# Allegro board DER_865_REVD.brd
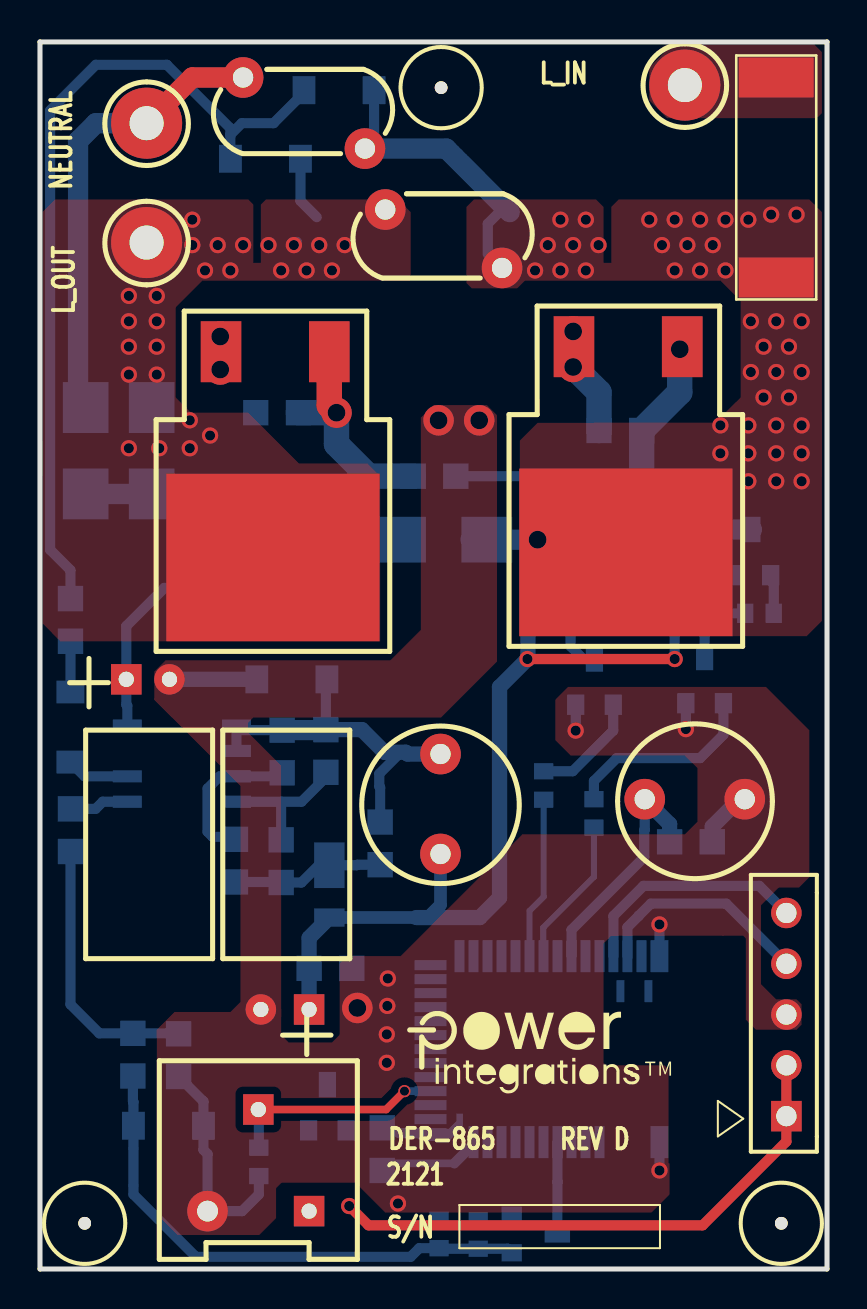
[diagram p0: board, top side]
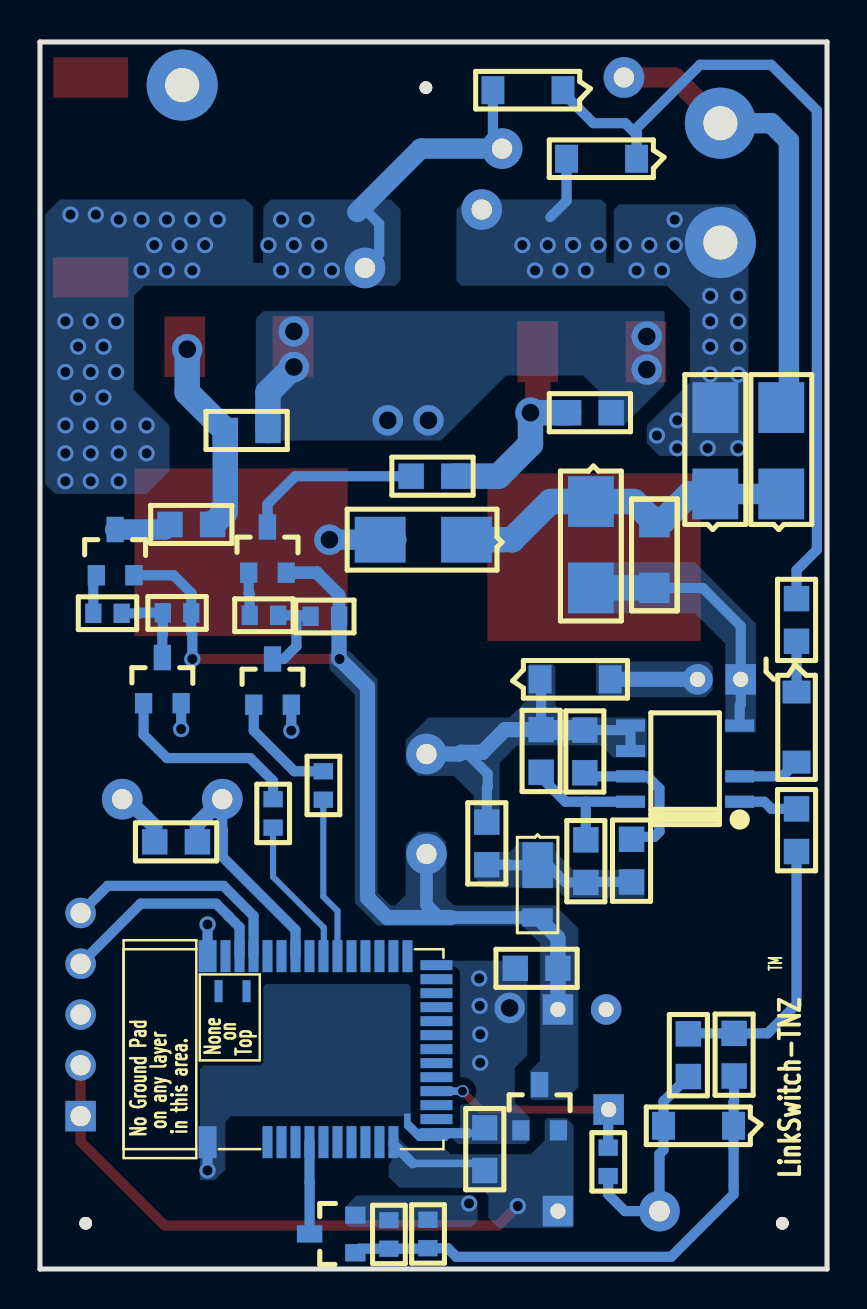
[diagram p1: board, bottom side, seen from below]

Outline 39.37 x 61.37 mm; copper layers: TOP, BOTTOM. Coordinates in mm from the lower left corner of the outline.
Outline path: 0,61.37 0,0 39.37,0 39.37,61.37 0,61.37

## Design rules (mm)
constraint set DEFAULT: min track width 0.508

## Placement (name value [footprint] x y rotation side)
C1  10 uF  [PISMC0805]  17.02 20.22 90 bottom
C2  100 nF  [PISMC0805]  12.12 24.82 90 bottom
C3  2.2 uF  [PIPOLCAPCYLD250LS100030]  6.73 29.49 180 top
C4  100 uF  [PIPOLCAPCYLD250LS100030#2]  11.05 12.98 0 top
C5  1 uF  [PISMC0805]  13.46 15.04 0 bottom
C6  10 uF  [PISMC0805]  17.12 7.06 270 bottom
C7  100 pF  [PISMC0603]  21.92 1.02 90 bottom
C8  100 pf  [PISMC0805]  6.93 11.76 270 bottom
C9  0.1 uF  [PISMC0805]  31.5 21.36 0 bottom
C10  100 nF  [PISMC0603]  10.95 4.65 90 bottom
D1  US2MA  [PISMDO214AC12]  2.29 38.76 90 bottom
D2  US2MA  [PISMDO214AC12]  18.03 36.47 0 bottom
D3  US2MA  [PISMDO214AC12]  5.59 38.76 90 bottom
D4  DFLR1600-7  [PISMDDFLR120012]  14.48 20.22 90 bottom
D5  SM4007PL-TP  [PI_SM_SOD-123_12]  9.53 55.52 0 bottom
D7  UFM15PL-TP  [PI_SM_SOD-123_12]  14.35 29.49 180 bottom
D8  SM4007PL-TP  [PI_SM_SOD-123_12]  13.21 58.95 0 bottom
F1  10 A  [PISMFUSE10P1X3P0]  36.83 59.59 270 top
J1  CON5  [PI_MOLEX_5]  37.34 7.65 90 top
L1  2.2 mH  [PI_CHOKE_2P_LS200D300]  20.04 25.75 270 top
MP1  Post, Round, 5mmL, NYL  [PISRSPACER_D125]  20.07 59.08 0 top
MP2  Post, Round, 5mmL, NYL  [PISRSPACER_D125]  2.24 2.29 0 top
MP3  Post, Round, 5mmL, NYL  [PISRSPACER_D125]  37.08 2.29 0 top
NOREF  -  []  18.39 13.34 0 top
NOREF#2  -  []  0 0 90 top
NOREF#3  -  []  -150.78 54.64 0 top
NOREF#4  -  []  -228.6 -144.37 0 top
NOREF#5  -  []  0 61.37 0 top
ON/OFF  SPST  (NO)  [PI_SWITCH_SPST_RND]  30.25 23.49 270 top
Q1  MMBT4403-7-F  [PISMSOT23123_1]  27.05 34.82 180 bottom
Q2  SIHB065N60E-GE3  [PISMDD2PAK]  14.48 45.87 180 top
Q3  MMBT4401LT1G  [PISMSOT23123_1]  26.8 28.22 180 bottom
Q4  MMBT4403-7-F  [PISMSOT23123_1]  34.67 34.7 180 bottom
Q5  MMBT4401LT1G  [PISMSOT23123_1]  32.31 28.3 180 bottom
Q6  SIHB065N60E-GE3  [PISMDD2PAK]  32.13 46.13 180 top
Q7  2N7002  [PISMSOT23123_1]  23.6 2.69 90 bottom
R1  25.5 k  [PISMR0805]  9.78 21.49 270 bottom
R2  10.0 k  [PISMR1206]  8.64 34.06 90 bottom
R3  49.9 k  [PISMR0805]  12.07 19.33 90 bottom
R4  40.2 k  [PISMR0805]  14.3 24.84 90 bottom
R5  10 k  [PISMR0603]  25.83 32.64 180 bottom
R6  10 k  [PISMR0603]  27.46 32.69 0 bottom
R7  10  [PISMR0805]  18.67 39.65 0 bottom
R8  1 k  [PISMR0603]  25.2 23.47 90 bottom
R9  510 k  [PISMR0805]  1.52 23.01 270 bottom
R10  10 k  [PISMR0805]  10.79 42.82 0 bottom
R11  510 k  [PISMR0805]  1.52 31.39 90 bottom
R12  100 k  [PISMR0805]  4.65 11.79 270 bottom
R13  510 k  [PISMR0603]  19.96 1.04 90 bottom
R14  10 k  [PISMR0603]  33.22 32.82 180 bottom
R15  10 k  [PISMR0603]  35.28 32.79 0 bottom
R16  10 k  [PISMR0805]  30.1 41.94 180 bottom
R17  10  [PISMR0805]  30.73 37.24 0 bottom
R18  1 k  [PISMR0603]  27.71 22.07 90 bottom
R19  100 k  [PIVRES9MMSQUARE]  13.46 2.9 0 top
RV1  275 Vac  [PIDISC350X160LS210X140040]  17.14 53.37 0 top
RV2  275 Vac  [PIDISC350X160LS210X140040#2]  10.16 59.59 0 top
TP1  WHT  [PITPKEYSTONE125X125]  5.33 57.3 0 top
TP2  RED  [PITPKEYSTONE125X125]  5.33 51.33 0 top
TP3  BLK  [PITPKEYSTONE125X125]  32.26 59.21 0 top
U1  LNK3302  [PISMSO8_NOP3]  4.37 23.37 90 bottom
U2  MDBT42Q  [PI_MOD_RAYTAC_MDBT42Q]  30.99 5.99 90 bottom
U3  MCP1703T-3002E/CB  [PISMSOT23132]  13.44 6.93 180 bottom
VR1  SMAZ10-13-F  [PISMDO214AC12]  11.81 38.38 270 bottom
VR2  MMSZ4693T1G  [PI_SM_SOD-123_12]  1.52 28.85 270 bottom
VR3  MMSZ4693T1G  [PI_SM_SOD-123_12]  4.67 7.16 0 bottom

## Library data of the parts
C1 C2 C5 C7-C10 = CAP NP
C3 C4 = CAP POL: alternate symbols: (pipolcapcyld250ls100030h)
C6 = CAP NP: room: 4
D1-D5 D7 D8 = DIODE
F1 = FUSE
J1 = CON5: alternate symbols: (berg_ps2_54_p5)
L1 = INDUCTOR
MP1-MP3 = SelfRetainingSpacer_3mmhole
ON/OFF = SW SPST
Q1 Q4 = PNP_BEC
Q2 Q6 = FET_N_GDS
Q3 Q5 = NPN_BEC
Q7 = FET_N_GSD
R1-R3 R9 R11-R13 = R
R4 = R: tolerance: 1%
R5-R8 R10 R14-R18 = R: room: 2
R19 = POT
RV1 RV2 = VARISTOR: alternate symbols: (pi_disc_354x220_ls220x10_040_h)
TP1-TP3 = TESTPOINT
U1 = LNK-TNZ
U2 = Mod_Raytac_MDBT42Q
U3 = MCP1754ST
VR1-VR3 = DIODE_ZENER

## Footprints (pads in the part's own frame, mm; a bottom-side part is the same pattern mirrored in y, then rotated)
PI_CHOKE_2P_LS200D300
  round 2.032 hole 1.016: 1(0,0) 2(4.999,0)
PI_MOD_RAYTAC_MDBT42Q
  rect 1.6x0.899 smd: 1(0.351,0) 39(9.649,0)
  rect 1.6x0.5 smd: 2(0.351,-3) 3(0.351,-3.701) 4(0.351,-4.399) 5(0.351,-5.1) 6(0.351,-5.799) 7(0.351,-6.5) 8(0.351,-7.201) 9(0.351,-7.899) 10(0.351,-8.6) 11(0.351,-9.299) 25(9.649,-10) 26(9.649,-9.299) 27(9.649,-8.6) 28(9.649,-7.899) 29(9.649,-7.201) 30(9.649,-6.5) 31(9.649,-5.799) 32(9.649,-5.1) 33(9.649,-4.399) 34(9.649,-3.701) 35(9.649,-3) 36(9.649,-2.301) 37(9.649,-1.6) 38(9.649,-0.899)
  rect 0.5x1.6 smd: 12(0.8,-11.45) 13(1.501,-11.45) 14(2.2,-11.45) 15(2.901,-11.45) 16(3.599,-11.45) 17(4.3,-11.45) 18(5.001,-11.45) 19(5.7,-11.45) 20(6.401,-11.45) 21(7.099,-11.45) 22(7.8,-11.45) 23(8.499,-11.45) 24(9.2,-11.45)
  rect 1.1x0.399 smd: 40(7.899,-0.551) 41(7.899,-1.951)
PI_MOLEX_5
  rect 1.524x1.524 hole 1.016: 1(0,0)
  round 1.524 hole 1.016: 2(2.54,0) 3(5.08,0) 4(7.62,0) 5(10.16,0)
PI_SM_SOD-123_12
  rect 1.143x1.397 smd: 1(0,0) 2(3.505,0)
PI_SWITCH_SPST_RND
  round 2.032 hole 1.016: 1(0,0) 2(0,5.004)
PIDISC350X160LS210X140040
  round 2.032 hole 1.016: 1(0.127,-0.381) 2(5.969,-3.302)
PIDISC350X160LS210X140040#2
  round 2.032 hole 1.016: 1(0,0) 2(6.096,-3.556)
PIPOLCAPCYLD250LS100030
  rect 1.524x1.524 hole 0.762: 1(2.413,0)
  round 1.524 hole 0.762: 2(0.254,0)
PIPOLCAPCYLD250LS100030#2
  rect 1.524x1.524 hole 0.762: 1(2.413,0)
  round 1.524 hole 0.762: 2(0,0)
PISMC0603
  rect 0.813x0.965 smd: 1(0,0) 2(1.422,0)
PISMC0805
  rect 1.27x1.27 smd: 1(0,0) 2(2.134,0)
PISMDD2PAK
  rect 2.032x3.048 smd: 1(0.005,0) 3(5.42,0)
  rect 10.668x8.382 smd: 2(2.824,10.287)
PISMDDFLR120012
  rect 2.286x1.524 smd: 1(-0.025,0)
  rect 0.914x1.524 smd: 2(-2.642,0)
PISMDO214AC12
  rect 2.54x2.286 smd: 1(0,0) 2(4.318,0)
PISMFUSE10P1X3P0
  rect 2x3.75 smd: 1(0,0) 2(10,0)
PISMR0603
  rect 0.813x0.965 smd: 1(0,0) 2(1.422,0)
PISMR0805
  rect 1.27x1.27 smd: 1(0,0) 2(2.134,0)
PISMR1206
  rect 1.524x1.524 smd: 1(0,0) 2(3.302,0)
PISMSO8_NOP3
  rect 0.61x1.448 smd: 1(0,0) 2(1.27,0) 4(3.81,0) 5(3.81,5.461) 6(2.54,5.461) 7(1.27,5.461) 8(0,5.461)
PISMSOT23123_1
  rect 0.864x1.016 smd: 1(-1.88,0) 2(0,0)
  rect 0.864x1.27 smd: 3(-0.94,2.286)
PISMSOT23132
  rect 0.864x1.016 smd: 1(-1.88,0) 2(0,0)
  rect 0.864x1.27 smd: 3(-0.94,2.286)
PISRSPACER_D125
  round 0.635 hole 3.175 unplated: (0,0)
PITPKEYSTONE125X125
  round 3.556 hole 1.702: 1(0,0)
PIVRES9MMSQUARE
  round 2.032 hole 1.041: 1(-5.08,0)
  rect 1.524x1.524 hole 0.762: 2(-2.54,5.08) 3(0,0)

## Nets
7V_OUT: C4.1 C5.1 D4.2 L1.2 Q1.2(EMITTER) Q4.2(EMITTER) R5.2 R14.2 U3.3
GND POWER: C3.2 C4.2 C5.2 C6.1 C7.2 C8.2 C9.2 C10.1 D7.2 J1.3 ON/OFF.2 Q2.3(S) Q3.2(EMITTER) Q5.2(EMITTER) Q6.3(S) Q7.2(S) R10.1 R13.2 R16.2 R19.1 U2.1 U2.12 U2.24 U2.39 U3.1 VR3.2
VCC: C6.2 J1.1 J1.2 R19.3 U2.11(VDD) U3.2(VOUT)
GATE_DRIVE: R8.1 U2.30
GATE_DRIVE2: R18.1 U2.31
SWDCLK: J1.5 U2.36
SWDIO: J1.4 U2.37
ZCD: Q7.3 U2.5
N140484: C3.1 R2.1 U1.4 VR1.2
N166085: D1.1 D2.1 D3.1 R2.2 VR1.1
N172951: F1.1 TP3.1
N285805: D3.2 D5.2 Q2.2 RV1.1 TP2.1
N295950: Q2.1 R7.1 R10.2
N325463: C1.2 C2.2 D7.1 L1.1 R4.2 U1.5 U1.6
N325534: C2.1 R1.1 U1.7
N325998: C1.1 D4.1 R1.2 R3.1
N326030: R3.2 R4.1 U1.8
N328031: C9.1 ON/OFF.1 U2.33
N332898: D2.2 D8.2 F1.2 Q6.2 RV1.2 RV2.2
N332994: Q6.1 R16.1 R17.1
N347733: D5.1 D8.1 R11.2
N354057: Q4.3 R17.2
N356858: Q1.3 R7.2
N356862: Q3.1 R8.2
N359869: Q1.1 R6.2
N360268: Q3.3 R5.1 R6.1
N361747: Q4.1 R15.2
N361751: Q5.3 R14.1 R15.1
N361818: Q5.1 R18.2
N547065: U1.2 VR2.2
N551285: C7.1 Q7.1 R12.2 R13.1 VR3.1
N551708: C8.1 R9.2 R12.1
N554020: R11.1 VR2.1
N554702: R9.1 U1.1
N560995: D1.2 RV2.1 TP1.1
N578362: C10.2 R19.2(WIPER) U2.15

Pads without a net: U2 2 3 4 6 7 8 9 10 13 14 16 17 18 19 20 21 22 23 25 26 27 28 29 32 34 35 38 40 41

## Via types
v1: diameter 0.61, hole 0.457, TOP to BOTTOM, 1 via
v2: diameter 0.813, hole 0.508, TOP to BOTTOM, 80 vias
v3: diameter 1.524, hole 0.889, TOP to BOTTOM, 10 vias

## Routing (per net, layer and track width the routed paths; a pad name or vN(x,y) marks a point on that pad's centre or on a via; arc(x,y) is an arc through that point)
7V_OUT: length 50.1
  TOP w0.508: v2(24.38,30.51) v2(31.75,30.51)
  BOTTOM w0.508: Q4.2 32.69,34.7 31.8,33.81 R14.2 31.8,31.83 31.75,31.78 v2(31.75,30.51)
  BOTTOM w0.635: 19.4,17.58 20.04,18.21 L1.2 ; 18.82,17.58 D4.2 ; Q1.2 25.53,34.82 24.41,33.71 R5.2
  BOTTOM w0.762: 18.82,17.58 22,17.58 22.99,18.57 22.99,29.11 v2(24.38,30.51) 24.41,30.53 R5.2 ; D4.2 13.46,16.56 C5.1 C4.1
GND POWER: length 29.4
  BOTTOM w0.508: 17.95,6.79 U2.12 ; v2(30.99,4.93) U2.1 ; C10.1 10.95,3.73 10.11,2.9 R19.1 8.38,5.75 8.18,5.96 VR3.2 8.18,8.38 C8.2 ; Q3.2 v2(26.8,26.92) ; v2(32.31,27) Q5.2 ; U2.39 v2(30.99,17.23)
  BOTTOM w0.762: C9.2 33.63,22.12 34.86,23.35 35.19,23.35 35.26,23.42 ON/OFF.2 ; D7.2 C3.2
  BOTTOM w1.27: v3(26.67,45.11) 26.7,45.11 27.97,43.84 R16.2
  vias: v2(17.4,14.53) v2(17.37,13.16) v2(17.35,11.73) v2(17.35,10.31) v2(17.91,3.28) v3(9.02,46.63) v3(9.02,44.98) v3(15.88,13.06) v3(19.94,42.44) v3(21.97,42.44) v3(26.67,46.89)
VCC: length 32.5
  TOP w0.508: v2(15.47,3.15) 16.43,2.18 33.15,2.18 37.34,6.38 J1.1 J1.2
  BOTTOM w0.381: 17.55,5.28 20.73,5.28
  BOTTOM w0.508: 20.73,5.28 21.69,6.25 U2.11
GATE_DRIVE: length 8.1
  BOTTOM w0.305: R8.1 25.2,18.62 24.49,17.91 U2.30
GATE_DRIVE2: length 7.5
  BOTTOM w0.305: U2.31 25.17,15.66 25.17,17.07 27.71,19.61 R18.1
SWDCLK: length 11.9
  BOTTOM w0.508: U2.36 28.69,17.66 30.19,19.16 35.98,19.16 J1.5
SWDIO: length 11.1
  BOTTOM w0.508: J1.4 34.33,18.27 30.56,18.27 29.95,17.66 29.95,17.65 29.39,17.09 U2.37
ZCD: length 4.6
  BOTTOM w0.508: Q7.3 25.88,4.34 25.89,4.35 U2.5
N140484: length 13.3
  BOTTOM w0.508: R2.1 6.22,34.06 4.32,32.16 C3.1 4.32,28.22 4.37,28.17 U1.4
  BOTTOM w1.27: VR1.2 R2.1
N166085: length 17.5
  BOTTOM w1.016: D3.1 D1.1
  BOTTOM w1.27: D3.1 6.86,38.76 8.26,37.36 R2.2 9.65,38.38 VR1.1 13.84,38.38 15.75,36.47 D2.1
N285805: length 3.5
  BOTTOM w0.508: 12.86,51.36 v2(12.7,51.21) ; D5.2 13.03,53.42 13.84,52.6
  vias: v2(4.44,48.67) v2(4.44,47.4) v2(4.44,46.13) v2(4.44,44.73) v2(4.44,41.05) v2(5.84,48.67) v2(5.84,47.4) v2(5.84,46.13) v2(5.84,44.73) v2(5.97,41.05) v2(7.49,42.44) v2(7.49,41.05) v2(7.62,52.48) v2(7.62,51.21) v2(8.26,49.94) v2(8.51,41.68) v2(8.89,51.21) v2(9.53,49.94) v2(10.16,51.21) v2(11.43,51.21) v2(12.07,49.94) v2(13.34,49.94) v2(13.97,51.21) v2(14.61,49.94) v2(15.24,51.21)
N295950: length 11.2
  TOP w1.27: v3(14.83,42.82) 14.47,43.19 Q2.1
  BOTTOM w1.27: R10.2 v3(14.83,42.82) 14.83,41.25 16.43,39.65 R7.1
N325463: length 19
  BOTTOM w0.508: U1.6 U1.5 10.06,26.95 C2.2 ; D7.1 14.35,29.36 14.3,29.31 R4.2 ; C1.2 17.02,24.08 16.97,24.13 16.97,24.76 17.96,25.75 18.38,25.75
  BOTTOM w0.762: R4.2 16.1,26.97 17.24,25.84 18.3,25.84 18.38,25.75 L1.1
  BOTTOM w1.016: C2.2 14.02,26.95 14.17,27.1 R4.2
N325534: length 7.8
  BOTTOM w0.508: R1.1 9.65,21.62 8.64,21.62 8.38,21.87 8.38,24.03 8.99,24.64 U1.7 11.94,24.64 C2.1
N325998: length 7.6
  BOTTOM w0.508: R1.2 12.04,19.35 R3.1 13.08,19.33 13.94,20.19 D4.1 15.85,20.19 15.88,20.22 C1.1
N326030: length 7.1
  BOTTOM w0.508: R4.1 14.3,24.59 13.08,23.37 12.07,23.37 ; 12.07,23.37 U1.8 ; 12.07,23.37 R3.2
N328031: length 12
  BOTTOM w0.508: U2.33 26.59,16.96 30.23,20.6 30.23,21.95 30.25,21.97 ON/OFF.1
  BOTTOM w0.762: C9.1 31.5,22.25 ON/OFF.1
N332898: length 17.7
  BOTTOM w0.508: 22.4,50.75 22.4,52.27 23.06,52.94 22.89,53.11 ; D8.2 16.71,56.49 RV2.2
  BOTTOM w1.016: 23.49,52.86 20.32,56.03 RV2.2 ; v3(24.89,36.47) D2.2 21.54,36.47
  vias: v2(24.77,49.94) v2(25.4,51.21) v2(26.04,52.48) v2(26.04,49.94) v2(26.67,51.21) v2(27.3,52.48) v2(27.3,49.94) v2(27.94,51.21) v2(30.48,52.48) v2(31.11,51.21) v2(31.75,52.48) v2(31.75,49.94) v2(32.39,51.21) v2(33.02,52.48) v2(33.02,49.94) v2(33.66,51.21) v2(34.04,42.19) v2(34.04,40.79) v2(34.29,52.48) v2(34.29,49.94) v2(35.43,52.48) v2(35.43,42.19) v2(35.43,40.79) v2(35.43,39.4) v2(35.56,47.4) v2(35.56,44.86) v2(36.2,46.13) v2(36.2,43.59) v2(36.58,52.73) v2(36.83,47.4) v2(36.83,44.86) v2(36.83,42.19) v2(36.83,40.79) v2(36.83,39.4) v2(37.47,46.13) v2(37.47,43.59) v2(37.85,52.73) v2(38.1,47.4) v2(38.1,44.86) v2(38.1,42.19) v2(38.1,40.79) v2(38.1,39.4)
N332994: length 9.8
  BOTTOM w1.27: v3(32,46) 32,43.84 R16.1 30.1,37.87 R17.1
N347733: length 42.3
  BOTTOM w0.508: 9.53,56.73 D5.1 ; 9.53,56.73 9.53,57.05 6.35,60.22 2.79,60.22 0.51,57.94 0.51,35.97 1.52,34.95 R11.2 ; 9.53,56.73 10.1,57.3 11.68,57.3 13.21,58.83 D8.1
N354057: length 2.8
  BOTTOM w1.016: R17.2 33.12,36.98 Q4.3
N356858: length 8.9
  BOTTOM w0.508: Q1.3 27.99,38.25 26.59,39.65 R7.2
N356862: length 5.6
  BOTTOM w0.508: R8.2 26.64,24.89 28.68,26.92 Q3.1
N359869: length 2.2
  BOTTOM w0.508: Q1.1 28.93,33.81 28.88,33.76 R6.2
N360268: length 4.7
  BOTTOM w0.508: 26.37,32.69 25.88,32.69 R5.1 ; 26.37,32.69 R6.1 ; 26.37,32.69 26.54,32.51 26.54,31.14 27.18,30.51 Q3.3
N361747: length 2
  BOTTOM w0.508: R15.2 36.7,34.26 36.68,34.29 36.68,34.57 Q4.1
N361751: length 4.3
  BOTTOM w0.508: Q5.3 33.25,31.72 33.22,31.75 R14.1 34.34,32.82 34.37,32.79 R15.1
N361818: length 9.9
  BOTTOM w0.508: R18.2 27.71,24.41 28.85,25.55 33.02,25.55 34.19,26.72 Q5.1
N547065: length 3.1
  BOTTOM w0.508: U1.2 2.24,24.64 VR2.2
N551285: length 28.4
  BOTTOM w0.381: 4.67,8.31 4.65,8.33 4.65,8.39 ; 4.67,4.17 4.65,4.19 4.65,5.99 4.67,6.02
  BOTTOM w0.508: R12.2 4.65,8.39 4.67,8.37 VR3.1 4.67,3.73 7.8,0.61 18.54,0.61 18.97,1.04 R13.1 19.99,1.02 C7.1 23.39,1.02 Q7.1
N551708: length 13.7
  BOTTOM w0.508: R9.2 1.52,13.23 2.97,11.79 R12.1 6.91,11.79 C8.1
N554020: length 2.5
  BOTTOM w0.508: R11.1 VR2.1
N554702: length 3
  BOTTOM w0.508: R9.1 2.78,23.01 3.14,23.37 U1.1
N560995: length 23.3
  TOP w1.016: RV2.1 7.62,59.59 TP1.1
  BOTTOM w1.016: TP1.1 2.79,57.3 1.91,56.41 1.91,43.85 2.16,43.6 2.16,43.21 D1.2 2.46,42.91
N578362: length 10.9
  TOP w0.381: R19.2 17.31,7.98 v1(18.23,8.9)
  BOTTOM w0.381: U2.15 v1(18.23,8.9)
  BOTTOM w0.508: C10.2 10.95,7.95 R19.2

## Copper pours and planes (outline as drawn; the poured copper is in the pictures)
7V_OUT on BOTTOM: 14.35,16.28 15.24,17.17 22.48,17.17 23.62,18.31 23.62,28.73 24.89,30 24.89,30.76 24.77,30.89 23.88,30.89 22.48,29.49 22.48,18.82 21.84,18.19 21.59,18.19 21.08,18.69 21.08,21.23 20.45,21.87 19.56,21.87 19.05,21.36 19.05,18.57 18.67,18.19 13.59,18.19 12.45,17.04 12.45,9.09 13.08,8.46 14.76,8.46 14.86,8.56 14.86,9.91 14.35,10.41
GND POWER on BOTTOM (solid shape): 21.16,7.09 20.47,6.4 19.02,6.4 18.8,6.63 18.8,7.01 20.45,7.01 20.83,7.39 20.83,7.77 21.16,7.77
GND POWER on TOP: 9.53,12.85 6.73,12.85 5.84,11.96 5.84,2.74 6.88,1.7 10.97,1.7 11.81,2.54 11.81,4.04 12.09,4.32 15.77,4.32 17.27,2.82 30.58,2.82 31.5,3.73 31.5,9.93 31.24,10.19 28.32,10.19 28.19,10.31 28.19,16.28 28.57,16.66 34.16,16.66 38.48,20.98 38.48,26.95 36.32,29.11 26.42,29.11 25.78,28.47 25.78,26.44 26.54,25.68 32.26,25.68 32.89,25.04 32.89,22.38 32.26,21.74 24.13,21.74 18.03,15.65 15.37,15.65 14.99,15.27 14.99,11.71 14.61,11.33 12.45,11.33 12.07,11.71 12.07,12.98 11.56,13.49 10.16,13.49
GND POWER on TOP: 19.68,43.21 22.35,43.21 22.86,42.7 22.86,30.38 20.07,27.58 6.6,27.58 5.71,28.47 5.71,29.87 6.29,30.44 17.53,30.44 19.05,31.97 19.05,42.57
GND POWER on TOP: 38.48,20.98 38.48,19.58 37.97,19.08 36.96,19.08 36.07,18.19 36.07,14.25 36.83,13.49 37.85,13.49 38.1,13.23 38.1,12.22 37.85,11.96 35.81,11.96 35.31,12.47 35.31,16.54 35.18,16.66 34.16,16.66 34.04,16.79 38.23,20.98
GND POWER on TOP: 5.71,28.47 10.03,24.16 10.03,12.6 10.54,12.09 11.56,12.09 12.07,12.6 12.07,25.17 10.41,26.82 10.41,27.33 10.67,27.58 10.67,27.97 9.27,27.97 8.38,28.85 5.87,28.85
GND POWER on BOTTOM: 20.83,7.65 20.83,14.12 20.95,14.25 28.07,14.25 28.19,14.12 28.19,10.34 28.35,10.19 31.17,10.19 31.37,9.98 31.37,4.44 30.63,4.44 30.1,4.98 30.1,7.37 29.82,7.65
GND POWER on BOTTOM: 17.73,3.68 17.48,3.43 17.48,2.41 17.78,2.11 23.9,2.11 24.08,2.29 24.08,3.12 23.52,3.68
GND POWER on BOTTOM: 20.32,15.42 15.37,15.42 14.99,15.04 14.99,10.69 15.62,10.06 15.62,8.33 14.88,7.59 14.88,6.43 15.06,6.25 18.47,6.25 18.77,6.55 20.35,6.55 20.35,7.01 20.32,7.04 18.49,7.04 18.36,7.16 18.36,14.73 18.57,14.94 20.32,14.94
GND POWER on BOTTOM: 5.97,30.38 11.43,30.38 11.56,30.25 11.56,28.85 11.3,28.6 6.1,28.6 5.71,28.98 5.71,30.12
GND POWER on BOTTOM: 8.13,47.9 28.19,47.9 28.57,47.52 28.57,41.43 19.3,41.43 16.05,44.68 12.19,44.68 11.43,43.92 11.43,42.19 10.16,42.19 8.13,44.22
VCC on BOTTOM: 21.92,6.27 21.92,4.6 21.39,4.06 17.35,4.06 16.94,3.66 16.94,2.57 16.43,2.06 12.75,2.06 12.67,2.13 12.67,7.19 13.03,7.54 14,7.54 14.12,7.42 14.12,6.43 14.81,5.74 18.82,5.74 19.1,6.02 20.9,6.02 21.54,6.65
N140484 on BOTTOM: 5.08,26.82 5.08,31.27 6.6,32.79 12.45,32.79 12.45,35.33 6.6,35.33 3.56,32.28 3.56,26.82
N172951 on TOP: 31.62,61.24 38.73,61.24 39.12,60.86 39.12,57.81 38.86,57.56 31.37,57.56 30.48,58.45 30.48,60.1
N285805 on TOP: 12.95,40.28 16.38,40.28 17.02,39.65 17.02,31.39 1.02,31.39 0.13,32.28 0.13,41.43 1.52,42.82 10.41,42.82
N285805 on TOP: 17.91,53.49 18.54,52.86 18.54,49.43 8.13,49.43 6.79,48.09 6.79,43.59 7.75,42.63 7.75,41.81 7.05,41.11 6.79,41.11 5.08,39.4 0.38,39.4 0.13,39.65 0.13,52.86 0.76,53.49 10.41,53.49 10.67,53.24 10.67,50.32 11.05,50.32 11.05,53.24 11.3,53.49
N285805 on BOTTOM: 6.6,44.6 9.02,42.19 9.02,41.3 8.38,40.67 4.32,40.67 3.94,41.05 3.94,42.82 5.71,44.6
N285805 on BOTTOM: 3.94,52.65 4.6,53.24 10.41,53.24 10.67,52.98 10.67,50.32 11.05,50.32 11.05,53.24 11.29,53.48 18.04,53.48 18.54,52.98 18.54,49.43 18.29,49.17 8,49.17 6.86,48.03 6.86,41.68 4.29,41.62 3.94,41.94
N325463 on BOTTOM: 9.02,25.55 10.67,25.55 11.3,26.19 15.49,26.19 16.38,25.3 16.38,21.74 17.65,21.74 17.65,23.65 18.67,24.66 20.45,24.66 21.08,25.3 21.08,26.44 19.94,27.58 15.88,27.58 14.99,28.47 14.99,30.12 14.86,30.25 13.72,30.25 13.59,30.12 13.59,28.22 12.95,27.58 9.14,27.58 9.02,27.46
N325998 on BOTTOM: 9.14,19.96 12.7,19.96 13.59,20.85 13.59,21.23 13.72,21.36 15.37,21.36 15.88,20.85 17.65,20.85 17.65,19.58 17.14,19.08 13.59,19.08 13.08,18.57 9.14,18.57
N332898 on TOP: 33.78,42.32 24.89,42.32 24,41.43 24,31.78 24.13,31.65 38.35,31.65 39.12,32.41 39.12,42.82 38.61,43.33 34.8,43.33
N332898 on TOP: 21.34,49.94 21.34,49.3 21.59,49.05 23.88,49.05 24.38,49.56 24.38,50.06 21.46,50.06
N332898 on TOP: 21.34,53.11 21.72,53.49 27.81,53.49 28.19,53.11 28.19,50.32 28.57,50.32 28.57,53.11 28.96,53.49 38.48,53.49 39.12,52.86 39.12,39.65 37.85,38.38 25.78,38.38 25.27,38.89 25.27,39.9 27.69,42.32 33.78,42.32 35.05,43.59 35.05,48.41 34.04,49.43 21.59,49.43 21.34,49.68
N332898 on BOTTOM: 39.12,39.27 39.12,52.73 38.35,53.49 29.08,53.49 28.7,53.11 28.7,50.32 28.22,50.32 28.19,53.11 27.81,53.49 21.84,53.49 21.34,52.98 21.34,49.43 21.59,49.17 34.16,49.17 34.67,48.67 34.67,43.97 32.89,42.19 32.89,39.9 34.04,38.76 38.61,38.76

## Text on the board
Ref Des/Silkscreen Bottom: TM | No Ground Pad | LinkSwitch-TNZ
Ref Des/Silkscreen Top: 2121 | S/N | DER-865 | L_IN | REV D | NEUTRAL | L_OUT
User.6: PLEASE DELETE THIS PIN | 14.  FAB HOUSE LOGO,DATE CODE TO BE IN SILK SCREEN ONLY.DO NOT USE COPPER. | 13.  MATERIAL FR4 DOUBLE SIDED COPPER 2oz THICKNESS 0.062" | 4.  SOLDER MASK LPI (LIQUID PHOTO IMAGEABLE) BOTH SIDES, COLOR BLUE.
User.9: FIGURE | FINISHED_SIZE | 18.0 | 20.0 | 30.0 | 35.0 | 40.0 | 41.0 | 67.0 | 125.0 | DRILL CHART: TOP to BOTTOM | ALL UNITS ARE IN MILS | TOLERANCE_DRILL | +3.0/-3.0 | +0.0/-0.0 | PLATED | NON-PLATED | QTY | 1 | 80 | 2 | 4 | 10 | 9 | 3
